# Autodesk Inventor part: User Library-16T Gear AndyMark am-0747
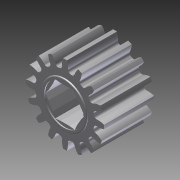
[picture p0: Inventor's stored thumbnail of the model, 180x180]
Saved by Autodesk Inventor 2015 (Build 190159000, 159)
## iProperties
Created: 2014-11
Part Number: User Library-16T Gear AndyMark am-0747
Material: Aluminum 6061
Document SubType Name: Modeling
Designer: Michael
Density: 2.71 g/cm^3
Appearance: Aluminum - Flat
Author: Windows User
Title: User Library-16T Gear AndyMark am-0747.STEP
Description: STEP AP214
Creation Date: 2014-11-06
Sending System: SolidWorks 2014
Preprocessor: SwSTEP 2.0
Author: Michael
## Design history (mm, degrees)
node "User Library-16T Gear AndyMark am-07471"
sketch "Sketch1"
  geometry: L1 (-12.109, 17.144)-(-11.449, 14.364); L2 (-11.56, 17.26)-(-10.739, 17.668); L3 (-10.739, 17.668)-(-10.049, 14.759); L4 (-10.049, 14.759)-(-10.006, 14.579); L5 (-12.912, 13.874)-(-13.694, 17.17); L6 (-13.694, 17.17)-(-12.651, 17.001); L7 (-11.56, 17.26)-(-10.739, 17.668); L8 (-10.739, 17.668)-(-10.006, 14.579); A1 r 8.573 centre (-9.469, 6.023) between (-9.363, 14.595) and (-10.204, 14.564) reference; A2 r 11.43 centre (-9.469, 6.023) between (-11.56, 17.26) and (-12.651, 17.001) reference; A3 r 8.573 centre (-9.469, 6.023) between (-12.651, 13.983) and (-13.416, 13.633) reference; A4 r 5 centre (-7.686, 16.413) between (-12.651, 17.001) and (-12.152, 14.165); A5 r 8.573 centre (-9.469, 6.023) between (-9.363, 14.595) and (-13.416, 13.633); A6 r 5 centre (-15.731, 14.504) between (-10.731, 14.502) and (-11.56, 17.26); A7 r 5 centre (-15.731, 14.504) between (-10.731, 14.502) and (-11.56, 17.26); A8 r 8.572 centre (-9.469, 6.023) between (-10.006, 14.579) and (-10.731, 14.502)
  constraints: 17 point on circle, 16 end point, 5 centre point, 2 collinear, 2 parallel, 2 symmetric about line, 1 concentric, 1 other
  dimensions: "d0" = 5 radius of A4
extrude "Extrusion1" cut sketch "Sketch1" stored distance "d1" = 10; taper "d2" = 0 deg
pattern_circular "Circular Pattern1" dims angle "d4" = 360 deg
fillet "Fillet1" dims "d6" = 0.79375
pattern_circular "Circular Pattern2" dims angle "d8" = 360 deg
workplane "Work Plane1"
body "Solid1"
node "Base1"
